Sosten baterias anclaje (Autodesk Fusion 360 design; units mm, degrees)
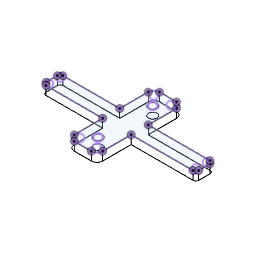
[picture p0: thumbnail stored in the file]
part number: 2026-07-18-00-36-31-481
sketch "Boceto1" plane through (0, 0, 0) normal (0, 0, 1) x axis (1, 0, 0)
  line L1 (0, 6) -> (0, 0)
  line L2 (49.5, 6) -> (0, 6)
  line L3 (49.5, 0) -> (49.5, 6)
  line L4 (0, 0) -> (49.5, 0)
  line L5 (25, 18) -> (25, 6)
  line L6 (30, 18) -> (25, 18)
  line L7 (30, -12) -> (30, 18)
  line L8 (20, -12) -> (30, -12)
  line L9 (20, 18) -> (20, -12)
  line L10 (25, 18) -> (20, 18)
  line L11 (25, 14.1) -> (25, 18)
  line L12 (25, 12.6) -> (25, 14.1)
  line L13 (25, -8.1) -> (25, -12)
  line L14 (25, -6.6) -> (25, -8.1)
  circle C1 centre (25, 12.6) radius 1.5
  circle C2 centre (25, -6.6) radius 1.5
  point P1 (0, 0)
  point P2 (0, 0)
  point P6 (25, 6)
  point P13 (25, 12.6)
  point P14 (25, 12.6)
  point P15 (25, -12)
  point P17 (25, -6.6)
  point P18 (25, -6.6)
  point P16 (25, -8.1)
  point P3 (0, 6)
  point P4 (49.5, 6)
  point P7 (25, 18)
  point P12 (25, 14.1)
  coincident P1 P2
  vertical L1
  perpendicular L1 L2
  perpendicular L2 L3
  perpendicular L1 L4
  coincident L2 P6
  perpendicular L2 L5
  perpendicular L5 L6
  perpendicular L2 L7
  perpendicular L7 L8
  perpendicular L4 L9
  perpendicular L5 L10
  perpendicular L6 L11
  parallel L5 L12
  coincident P13 P14
  midpoint L8 P15
  perpendicular L8 L13
  parallel L13 L14
  coincident P17 P18
  coincident P16 C2
  dimension "d1" distance P2 P3 = 6
  dimension "d2" distance P3 P4 = 49.5
  dimension "d3" distance P6 P7 = 12
  dimension "d4" distance P7 P12 = 3.9
  dimension "d5" distance P12 P13 = 1.5
  dimension "d6" diameter C1 = 3
  dimension "d7" distance P15 P16 = 3.9
  dimension "d8" distance P16 P17 = 1.5
extrude "Extruir1" new body sketch "Boceto1" profile of L1 L2 L3 L4 L5 L6 L7 L8 L9 L10 L11 C1 L13 C2 along normal blind 3
extrude "Extruir2" cut of existing geometry blind -0.25
extrude "Extruir3" add of existing geometry blind 0.25
sketch "Boceto2" plane through (0, 0, 3) normal (0, 0, 1) x axis (-1, 0, 0)
  line L1 (-0.25, 0) -> (-0.25, -6)
  line L2 (-20, 0) -> (-0.25, 0)
  line L3 (-20, 12) -> (-20, 0)
  line L4 (-30, 12) -> (-20, 12)
  line L5 (-30, 0) -> (-30, 12)
  line L6 (-49.75, 0) -> (-30, 0)
  line L7 (-49.75, -6) -> (-49.75, 0)
  line L8 (-30, -6) -> (-49.75, -6)
  line L9 (-30, -18) -> (-30, -6)
  line L10 (-20, -18) -> (-30, -18)
  line L11 (-20, -6) -> (-20, -18)
  line L12 (-0.25, -6) -> (-20, -6)
  circle C1 centre (-25, -12.6) radius 1.5
  circle C2 centre (-25, 6.6) radius 1.5
fillet "Empalme1" radius 2
extrude "Extruir4" add of existing geometry blind 3
extrude "Extruir5" add of existing geometry blind 1.2
sketch "Boceto3" plane through (0, 0, 3) normal (0, 0, 1) x axis (-1, 0, 0)
fillet "Empalme2" radius 1
sketch "Boceto4" plane through (0, 0, 3) normal (0, 0, 1) x axis (-1, 0, 0)
  line L1 (0.95, -1) -> (0.95, -5)
  line L2 (-20, 0) -> (-0.05, 0)
  line L3 (-20, 10) -> (-20, 0)
  line L4 (-28, 12) -> (-22, 12)
  line L5 (-30, 0) -> (-30, 10)
  line L6 (-51.75, 0) -> (-30, 0)
  line L7 (-52.75, -5) -> (-52.75, -1)
  line L8 (-30, -6) -> (-51.75, -6)
  line L9 (-30, -16) -> (-30, -6)
  line L10 (-22, -18) -> (-28, -18)
  line L11 (-20, -6) -> (-20, -16)
  line L12 (-0.05, -6) -> (-20, -6)
  arc A1 centre (-0.05, -5) radius 1 clockwise from (0.95, -5) to (-0.05, -6)
  arc A2 centre (-0.05, -1) radius 1 clockwise from (-0.05, 0) to (0.95, -1)
  arc A3 centre (-22, 10) radius 2 clockwise from (-22, 12) to (-20, 10)
  arc A4 centre (-28, 10) radius 2 clockwise from (-30, 10) to (-28, 12)
  arc A5 centre (-51.75, -1) radius 1 clockwise from (-52.75, -1) to (-51.75, 0)
  arc A6 centre (-51.75, -5) radius 1 clockwise from (-51.75, -6) to (-52.75, -5)
  arc A7 centre (-28, -16) radius 2 clockwise from (-28, -18) to (-30, -16)
  arc A8 centre (-22, -16) radius 2 clockwise from (-20, -16) to (-22, -18)
  circle C1 centre (-25, -12.6) radius 1.5
  circle C2 centre (-25, 6.6) radius 1.5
